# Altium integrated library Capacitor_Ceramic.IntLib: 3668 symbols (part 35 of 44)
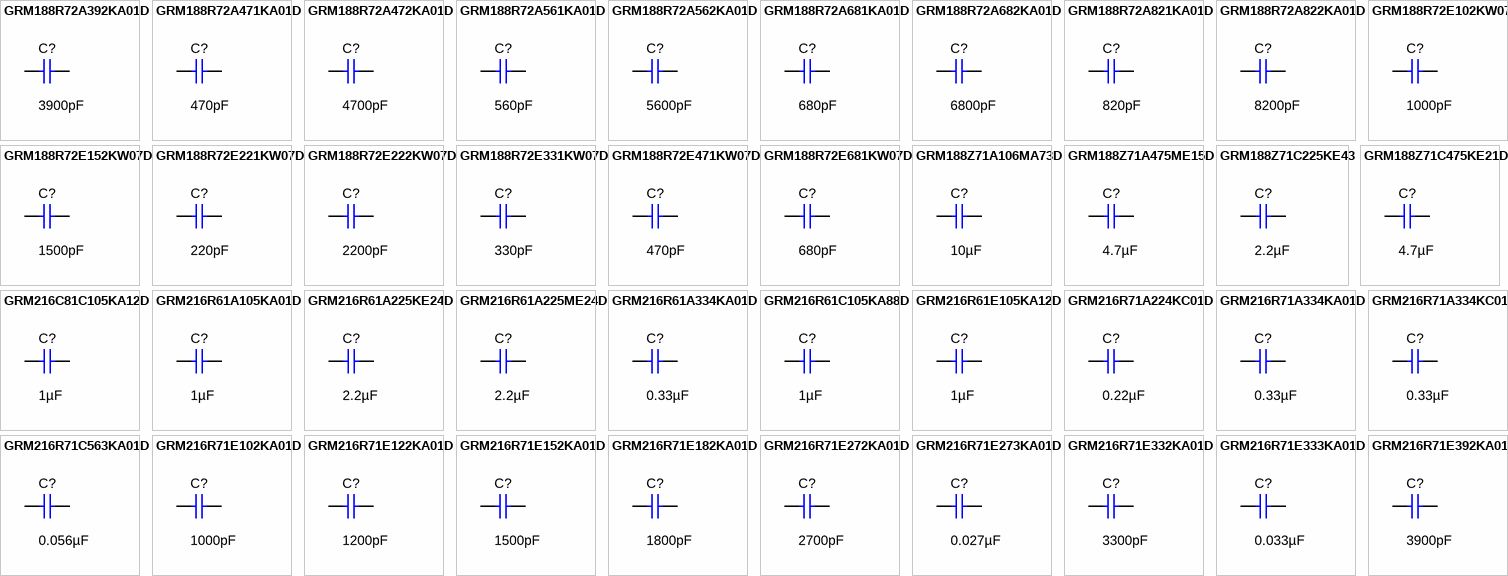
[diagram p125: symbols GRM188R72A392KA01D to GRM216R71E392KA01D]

## GRM188R72A822KA01D
designator C?  ValueDisplayed: 8200pF  (hidden comment: GRM188R72A822KA01D)
CAP, CERM, 8200 pF, 100 V,+/- 10%, X7R, 0603; Manufacturer: MuRata; Polarized: N; CompType: Capacitor; Value: 8200pF; U/M: EA; Cap_F: 0.0000000082; Tolerance_%: 10; VDC_V: 100; Value2: 100V; TaMin_C: -55; TaMax_C: 125; Cap_Case: 0603; SizeArea_mm2: 1.28; SizeAreaWB_mm2: 4.68; SizeX_mm: 1.6; SizeY_mm: 0.8; SizeZ_mm: 1; AEC Category: Q200
signal-integrity model Cap
simulation model Cap
footprint 0603
footprint 0603M
footprint 0603L
footprint 0603_HV
footprint 0603S
pins: 1, 2

## GRM188R72E102KW07D
designator C?  ValueDisplayed: 1000pF  (hidden comment: GRM188R72E102KW07D)
CAP, CERM, 1000 pF, 250 V,+/- 10%, X7R, 0603; Manufacturer: MuRata; Polarized: N; CompType: Capacitor; Value: 1000pF; U/M: EA; Cap_F: 0.000000001; Tolerance_%: 10; VDC_V: 250; Value2: 250V; TaMin_C: -55; TaMax_C: 125; Cap_Case: 0603; SizeArea_mm2: 1.28; SizeAreaWB_mm2: 4.68; SizeX_mm: 1.6; SizeY_mm: 0.8; SizeZ_mm: 1; AEC Category: Q200
signal-integrity model Cap
simulation model Cap
footprint 0603
footprint 0603M
footprint 0603L
footprint 0603_HV
footprint 0603S
pins: 1, 2

## GRM188R72E152KW07D
designator C?  ValueDisplayed: 1500pF  (hidden comment: GRM188R72E152KW07D)
CAP, CERM, 1500 pF, 250 V,+/- 10%, X7R, 0603; Manufacturer: MuRata; Polarized: N; CompType: Capacitor; Value: 1500pF; U/M: EA; Cap_F: 0.0000000015; Tolerance_%: 10; VDC_V: 250; Value2: 250V; TaMin_C: -55; TaMax_C: 125; Cap_Case: 0603; SizeArea_mm2: 1.28; SizeAreaWB_mm2: 4.68; SizeX_mm: 1.6; SizeY_mm: 0.8; SizeZ_mm: 1; AEC Category: Q200
signal-integrity model Cap
simulation model Cap
footprint 0603
footprint 0603M
footprint 0603L
footprint 0603_HV
footprint 0603S
pins: 1, 2

## GRM188R72E221KW07D
designator C?  ValueDisplayed: 220pF  (hidden comment: GRM188R72E221KW07D)
CAP, CERM, 220 pF, 250 V,+/- 10%, X7R, 0603; Manufacturer: MuRata; Polarized: N; CompType: Capacitor; Value: 220pF; U/M: EA; Cap_F: 0.00000000022; Tolerance_%: 10; VDC_V: 250; Value2: 250V; TaMin_C: -55; TaMax_C: 125; Cap_Case: 0603; SizeArea_mm2: 1.28; SizeAreaWB_mm2: 4.68; SizeX_mm: 1.6; SizeY_mm: 0.8; SizeZ_mm: 1; AEC Category: Q200
signal-integrity model Cap
simulation model Cap
footprint 0603
footprint 0603M
footprint 0603L
footprint 0603_HV
footprint 0603S
pins: 1, 2

## GRM188R72E222KW07D
designator C?  ValueDisplayed: 2200pF  (hidden comment: GRM188R72E222KW07D)
CAP, CERM, 2200 pF, 250 V,+/- 10%, X7R, 0603; Manufacturer: MuRata; Polarized: N; CompType: Capacitor; Value: 2200pF; U/M: EA; Cap_F: 0.0000000022; Tolerance_%: 10; VDC_V: 250; Value2: 250V; TaMin_C: -55; TaMax_C: 125; Cap_Case: 0603; SizeArea_mm2: 1.28; SizeAreaWB_mm2: 4.68; SizeX_mm: 1.6; SizeY_mm: 0.8; SizeZ_mm: 1; AEC Category: Q200
signal-integrity model Cap
simulation model Cap
footprint 0603
footprint 0603M
footprint 0603L
footprint 0603_HV
footprint 0603S
pins: 1, 2

## GRM188R72E331KW07D
designator C?  ValueDisplayed: 330pF  (hidden comment: GRM188R72E331KW07D)
CAP, CERM, 330 pF, 250 V,+/- 10%, X7R, 0603; Manufacturer: MuRata; Polarized: N; CompType: Capacitor; Value: 330pF; U/M: EA; Cap_F: 0.00000000033; Tolerance_%: 10; VDC_V: 250; Value2: 250V; TaMin_C: -55; TaMax_C: 125; Cap_Case: 0603; SizeArea_mm2: 1.28; SizeAreaWB_mm2: 4.68; SizeX_mm: 1.6; SizeY_mm: 0.8; SizeZ_mm: 1; AEC Category: Q200
signal-integrity model Cap
simulation model Cap
footprint 0603
footprint 0603M
footprint 0603L
footprint 0603_HV
footprint 0603S
pins: 1, 2

## GRM188R72E471KW07D
designator C?  ValueDisplayed: 470pF  (hidden comment: GRM188R72E471KW07D)
CAP, CERM, 470 pF, 250 V,+/- 10%, X7R, 0603; Manufacturer: MuRata; Polarized: N; CompType: Capacitor; Value: 470pF; U/M: EA; Cap_F: 0.00000000047; Tolerance_%: 10; VDC_V: 250; Value2: 250V; TaMin_C: -55; TaMax_C: 125; Cap_Case: 0603; SizeArea_mm2: 1.28; SizeAreaWB_mm2: 4.68; SizeX_mm: 1.6; SizeY_mm: 0.8; SizeZ_mm: 1; AEC Category: Q200; Green_Lifecycle: Not Set; Green_REACh: Incomplete
signal-integrity model Cap
simulation model Cap
footprint 0603
footprint 0603M
footprint 0603L
footprint 0603_HV
footprint 0603S
pins: 1, 2

## GRM188R72E681KW07D
designator C?  ValueDisplayed: 680pF  (hidden comment: GRM188R72E681KW07D)
CAP, CERM, 680 pF, 250 V,+/- 10%, X7R, 0603; Manufacturer: MuRata; Polarized: N; CompType: Capacitor; Value: 680pF; U/M: EA; Cap_F: 0.00000000068; Tolerance_%: 10; VDC_V: 250; Value2: 250V; TaMin_C: -55; TaMax_C: 125; Cap_Case: 0603; SizeArea_mm2: 1.28; SizeAreaWB_mm2: 4.68; SizeX_mm: 1.6; SizeY_mm: 0.8; SizeZ_mm: 1; AEC Category: Q200
signal-integrity model Cap
simulation model Cap
footprint 0603
footprint 0603M
footprint 0603L
footprint 0603_HV
footprint 0603S
pins: 1, 2

## GRM188Z71A106MA73D
designator C?  ValueDisplayed: 10µF  (hidden comment: GRM188Z71A106MA73D)
CAP, CERM, 10 µF, 10 V,+/- 20%, X7R, 0603; Manufacturer: MuRata; Polarized: N; CompType: Capacitor; Value: 10uF; U/M: EA; Cap_F: 0.00001; Tolerance_%: 20; VDC_V: 10; Value2: 10V; TaMin_C: -55; TaMax_C: 125; Cap_Case: 0603; SizeArea_mm2: 1.28; SizeAreaWB_mm2: 4.68; SizeX_mm: 1.6; SizeY_mm: 0.8; SizeZ_mm: 1; AEC Category: Q200; Green_Lifecycle: Active; Green_REACh: Passed
signal-integrity model Cap
simulation model Cap
footprint 0603
footprint 0603M
footprint 0603L
footprint 0603_HV
footprint 0603S
pins: 1, 2

## GRM188Z71A475ME15D
designator C?  ValueDisplayed: 4.7µF  (hidden comment: GRM188Z71A475ME15D)
CAP, CERM, 4.7 µF, 10 V,+/- 20%, X7R, 0603; Manufacturer: MuRata; Polarized: N; CompType: Capacitor; Value: 4.7uF; U/M: EA; Cap_F: 0.0000047; Tolerance_%: 20; VDC_V: 10; Value2: 10V; TaMin_C: -55; TaMax_C: 125; Cap_Case: 0603; SizeArea_mm2: 1.28; SizeAreaWB_mm2: 4.68; SizeX_mm: 1.6; SizeY_mm: 0.8; SizeZ_mm: 1; AEC Category: Q200
signal-integrity model Cap
simulation model Cap
footprint 0603
footprint 0603M
footprint 0603L
footprint 0603_HV
footprint 0603S
pins: 1, 2

## GRM188Z71C225KE43
designator C?  ValueDisplayed: 2.2µF  (hidden comment: GRM188Z71C225KE43)
CAP, CERM, 2.2 µF, 16 V,+/- 10%, X7R, 0603; Manufacturer: MuRata; Polarized: N; CompType: Capacitor; Value: 2.2uF; U/M: EA; Cap_F: 0.0000022; Tolerance_%: 10; VDC_V: 16; Value2: 16V; TaMin_C: -55; TaMax_C: 125; Cap_Case: 0603; SizeArea_mm2: 1.28; SizeAreaWB_mm2: 4.68; SizeX_mm: 1.6; SizeY_mm: 0.8; SizeZ_mm: 1; AEC Category: Q200; Green_Lifecycle: Active; Green_REACh: Passed
signal-integrity model Cap
simulation model Cap
footprint 0603
footprint 0603M
footprint 0603L
footprint 0603_HV
footprint 0603S
pins: 1, 2

## GRM188Z71C475KE21D
designator C?  ValueDisplayed: 4.7µF  (hidden comment: GRM188Z71C475KE21D)
CAP, CERM, 4.7 µF, 16 V,+/- 10%, X7R, 0603; Manufacturer: MuRata; Polarized: N; CompType: Capacitor; Value: 4.7uF; U/M: EA; Cap_F: 0.0000047; Tolerance_%: 10; VDC_V: 16; Value2: 16V; TaMin_C: -55; TaMax_C: 125; Cap_Case: 0603; SizeArea_mm2: 1.28; SizeAreaWB_mm2: 4.68; SizeX_mm: 1.6; SizeY_mm: 0.8; SizeZ_mm: 1; AEC Category: Q200
signal-integrity model Cap
simulation model Cap
footprint 0603
footprint 0603M
footprint 0603L
footprint 0603_HV
footprint 0603S
pins: 1, 2

## GRM216C81C105KA12D
designator C?  ValueDisplayed: 1µF  (hidden comment: GRM216C81C105KA12D)
CAP, CERM, 1 µF, 16 V,+/- 10%, X6S, 0805; Manufacturer: MuRata; Polarized: N; CompType: Capacitor; Value: 1uF; U/M: EA; Cap_F: 0.000001; Tolerance_%: 10; VDC_V: 16; Value2: 16V; TaMin_C: -55; TaMax_C: 105; Cap_Case: 0805; SizeArea_mm2: 2.5; SizeAreaWB_mm2: 6.75; SizeX_mm: 2; SizeY_mm: 1.25; SizeZ_mm: 1.45; AEC Category: Q200
signal-integrity model Cap
simulation model Cap
footprint 0805_HV
footprint 0805_HV1
footprint 0805
footprint 0805M
footprint 0805L
pins: 1, 2

## GRM216R61A105KA01D
designator C?  ValueDisplayed: 1µF  (hidden comment: GRM216R61A105KA01D)
CAP, CERM, 1 µF, 10 V,+/- 10%, X5R, 0805; Manufacturer: MuRata; Polarized: N; CompType: Capacitor; Value: 1uF; U/M: EA; Cap_F: 0.000001; Tolerance_%: 10; Value2: 10V; TaMin_C: -55; TaMax_C: 85; Cap_Case: 0805; SizeArea_mm2: 2.5; SizeAreaWB_mm2: 6.75; SizeX_mm: 2; SizeY_mm: 1.25; SizeZ_mm: 1.45; AEC Category: Q200; Green_Lifecycle: Active; Green_REACh: Passed
signal-integrity model Cap
simulation model Cap
footprint 0805_HV
footprint 0805_HV1
footprint 0805
footprint 0805M
footprint 0805L
pins: 1, 2

## GRM216R61A225KE24D
designator C?  ValueDisplayed: 2.2µF  (hidden comment: GRM216R61A225KE24D)
CAP, CERM, 2.2 µF, 10 V,+/- 10%, X5R, 0805; Manufacturer: MuRata; Polarized: N; CompType: Capacitor; Value: 2.2uF; U/M: EA; Cap_F: 0.0000022; Tolerance_%: 10; ESR_ohm: 0.009; Value1: 0.009 ohm; Value2: 10V; TaMin_C: -55; TaMax_C: 85; Cap_Case: 0805; SizeArea_mm2: 2.5; SizeAreaWB_mm2: 6.75; SizeX_mm: 2; SizeY_mm: 1.25; SizeZ_mm: 1.45; AEC Category: Q200; Green_Lifecycle: Active; Green_REACh: Passed
signal-integrity model Cap
simulation model Cap
footprint 0805_HV
footprint 0805_HV1
footprint 0805
footprint 0805M
footprint 0805L
pins: 1, 2

## GRM216R61A225ME24D
designator C?  ValueDisplayed: 2.2µF  (hidden comment: GRM216R61A225ME24D)
CAP, CERM, 2.2 µF, 10 V,+/- 20%, X5R, 0805; Manufacturer: MuRata; Polarized: N; CompType: Capacitor; Value: 2.2uF; U/M: EA; Cap_F: 0.0000022; Tolerance_%: 20; ESR_ohm: 0.009; Value1: 0.009 ohm; VDC_V: 10; Value2: 10V; TaMin_C: -55; TaMax_C: 85; Cap_Case: 0805; SizeArea_mm2: 2.5; SizeAreaWB_mm2: 6.75; SizeX_mm: 2; SizeY_mm: 1.25; SizeZ_mm: 1.45; AEC Category: Q200
signal-integrity model Cap
simulation model Cap
footprint 0805_HV
footprint 0805_HV1
footprint 0805
footprint 0805M
footprint 0805L
pins: 1, 2

## GRM216R61A334KA01D
designator C?  ValueDisplayed: 0.33µF  (hidden comment: GRM216R61A334KA01D)
CAP, CERM, 0.33 µF, 10 V,+/- 10%, X5R, 0805; Manufacturer: MuRata; Polarized: N; CompType: Capacitor; Value: 0.33uF; U/M: EA; Cap_F: 0.00000033; Tolerance_%: 10; Value2: 10V; TaMin_C: -55; TaMax_C: 85; Cap_Case: 0805; SizeArea_mm2: 2.5; SizeAreaWB_mm2: 6.75; SizeX_mm: 2; SizeY_mm: 1.25; SizeZ_mm: 1.45; AEC Category: Q200
signal-integrity model Cap
simulation model Cap
footprint 0805_HV
footprint 0805_HV1
footprint 0805
footprint 0805M
footprint 0805L
pins: 1, 2

## GRM216R61C105KA88D
designator C?  ValueDisplayed: 1µF  (hidden comment: GRM216R61C105KA88D)
CAP, CERM, 1 µF, 16 V,+/- 10%, X5R, 0805; Manufacturer: MuRata; Polarized: N; CompType: Capacitor; Value: 1uF; U/M: EA; Cap_F: 0.000001; Tolerance_%: 10; VDC_V: 16; Value2: 16V; TaMin_C: -55; TaMax_C: 85; Cap_Case: 0805; SizeArea_mm2: 2.5; SizeAreaWB_mm2: 6.75; SizeX_mm: 2; SizeY_mm: 1.25; SizeZ_mm: 1.45; AEC Category: Q200
signal-integrity model Cap
simulation model Cap
footprint 0805_HV
footprint 0805_HV1
footprint 0805
footprint 0805M
footprint 0805L
pins: 1, 2

## GRM216R61E105KA12D
designator C?  ValueDisplayed: 1µF  (hidden comment: GRM216R61E105KA12D)
CAP, CERM, 1 µF, 25 V,+/- 10%, X5R, 0805; Manufacturer: MuRata; Polarized: N; CompType: Capacitor; Value: 1uF; U/M: EA; Cap_F: 0.000001; Tolerance_%: 10; ESR_ohm: 0.009; Value1: 0.009 ohm; VDC_V: 25; Value2: 25V; TaMin_C: -55; TaMax_C: 85; Cap_Case: 0805; SizeArea_mm2: 2.5; SizeAreaWB_mm2: 6.75; SizeX_mm: 2; SizeY_mm: 1.25; SizeZ_mm: 1.45; AEC Category: Q200; Green_Lifecycle: Active; Green_REACh: Passed
signal-integrity model Cap
simulation model Cap
footprint 0805_HV
footprint 0805_HV1
footprint 0805
footprint 0805M
footprint 0805L
pins: 1, 2

## GRM216R71A224KC01D
designator C?  ValueDisplayed: 0.22µF  (hidden comment: GRM216R71A224KC01D)
CAP, CERM, 0.22 µF, 10 V,+/- 10%, X7R, 0805; Manufacturer: MuRata; Polarized: N; CompType: Capacitor; Value: 0.22uF; U/M: EA; Cap_F: 0.00000022; Tolerance_%: 10; Value2: 10V; TaMin_C: -55; TaMax_C: 125; Cap_Case: 0805; SizeArea_mm2: 2.5; SizeAreaWB_mm2: 6.75; SizeX_mm: 2; SizeY_mm: 1.25; SizeZ_mm: 1.45; AEC Category: Q200
signal-integrity model Cap
simulation model Cap
footprint 0805_HV
footprint 0805_HV1
footprint 0805
footprint 0805M
footprint 0805L
pins: 1, 2

## GRM216R71A334KA01D
designator C?  ValueDisplayed: 0.33µF  (hidden comment: GRM216R71A334KA01D)
CAP, CERM, 0.33 µF, 10 V,+/- 10%, X7R, 0805; Manufacturer: MuRata; Polarized: N; CompType: Capacitor; Value: 0.33uF; U/M: EA; Cap_F: 0.00000033; Tolerance_%: 10; Value2: 10V; TaMin_C: -55; TaMax_C: 125; Cap_Case: 0805; SizeArea_mm2: 2.5; SizeAreaWB_mm2: 6.75; SizeX_mm: 2; SizeY_mm: 1.25; SizeZ_mm: 1.45; AEC Category: Q200
signal-integrity model Cap
simulation model Cap
footprint 0805_HV
footprint 0805_HV1
footprint 0805
footprint 0805M
footprint 0805L
pins: 1, 2

## GRM216R71A334KC01D
designator C?  ValueDisplayed: 0.33µF  (hidden comment: GRM216R71A334KC01D)
CAP, CERM, 0.33 µF, 10 V,+/- 10%, X7R, 0805; Manufacturer: MuRata; Polarized: N; CompType: Capacitor; Value: 0.33uF; U/M: EA; Cap_F: 0.00000033; Tolerance_%: 10; Value2: 10V; TaMin_C: -55; TaMax_C: 125; Cap_Case: 0805; SizeArea_mm2: 2.5; SizeAreaWB_mm2: 6.75; SizeX_mm: 2; SizeY_mm: 1.25; SizeZ_mm: 1.45; AEC Category: Q200
signal-integrity model Cap
simulation model Cap
footprint 0805_HV
footprint 0805_HV1
footprint 0805
footprint 0805M
footprint 0805L
pins: 1, 2

## GRM216R71C563KA01D
designator C?  ValueDisplayed: 0.056µF  (hidden comment: GRM216R71C563KA01D)
CAP, CERM, 0.056 µF, 16 V,+/- 10%, X7R, 0805; Manufacturer: MuRata; Polarized: N; CompType: Capacitor; Value: 0.056uF; U/M: EA; Cap_F: 0.000000056; Tolerance_%: 10; VDC_V: 16; Value2: 16V; TaMin_C: -55; TaMax_C: 125; Cap_Case: 0805; SizeArea_mm2: 2.5; SizeAreaWB_mm2: 6.75; SizeX_mm: 2; SizeY_mm: 1.25; SizeZ_mm: 1.45; AEC Category: Q200
signal-integrity model Cap
simulation model Cap
footprint 0805_HV
footprint 0805_HV1
footprint 0805
footprint 0805M
footprint 0805L
pins: 1, 2

## GRM216R71E102KA01D
designator C?  ValueDisplayed: 1000pF  (hidden comment: GRM216R71E102KA01D)
CAP, CERM, 1000 pF, 25 V,+/- 10%, X7R, 0805; Manufacturer: MuRata; Polarized: N; CompType: Capacitor; Value: 1000pF; U/M: EA; Cap_F: 0.000000001; Tolerance_%: 10; VDC_V: 25; Value2: 25V; TaMin_C: -55; TaMax_C: 125; Cap_Case: 0805; SizeArea_mm2: 2.5; SizeAreaWB_mm2: 6.75; SizeX_mm: 2; SizeY_mm: 1.25; SizeZ_mm: 1.45; AEC Category: Q200; Green_Lifecycle: Active; Green_REACh: Passed
signal-integrity model Cap
simulation model Cap
footprint 0805_HV
footprint 0805_HV1
footprint 0805
footprint 0805M
footprint 0805L
pins: 1, 2

## GRM216R71E122KA01D
designator C?  ValueDisplayed: 1200pF  (hidden comment: GRM216R71E122KA01D)
CAP, CERM, 1200 pF, 25 V,+/- 10%, X7R, 0805; Manufacturer: MuRata; Polarized: N; CompType: Capacitor; Value: 1200pF; U/M: EA; Cap_F: 0.0000000012; Tolerance_%: 10; VDC_V: 25; Value2: 25V; TaMin_C: -55; TaMax_C: 125; Cap_Case: 0805; SizeArea_mm2: 2.5; SizeAreaWB_mm2: 6.75; SizeX_mm: 2; SizeY_mm: 1.25; SizeZ_mm: 1.45; AEC Category: Q200
signal-integrity model Cap
simulation model Cap
footprint 0805_HV
footprint 0805_HV1
footprint 0805
footprint 0805M
footprint 0805L
pins: 1, 2

## GRM216R71E152KA01D
designator C?  ValueDisplayed: 1500pF  (hidden comment: GRM216R71E152KA01D)
CAP, CERM, 1500 pF, 25 V,+/- 10%, X7R, 0805; Manufacturer: MuRata; Polarized: N; CompType: Capacitor; Value: 1500pF; U/M: EA; Cap_F: 0.0000000015; Tolerance_%: 10; VDC_V: 25; Value2: 25V; TaMin_C: -55; TaMax_C: 125; Cap_Case: 0805; SizeArea_mm2: 2.5; SizeAreaWB_mm2: 6.75; SizeX_mm: 2; SizeY_mm: 1.25; SizeZ_mm: 1.45; AEC Category: Q200
signal-integrity model Cap
simulation model Cap
footprint 0805_HV
footprint 0805_HV1
footprint 0805
footprint 0805M
footprint 0805L
pins: 1, 2

## GRM216R71E182KA01D
designator C?  ValueDisplayed: 1800pF  (hidden comment: GRM216R71E182KA01D)
CAP, CERM, 1800 pF, 25 V,+/- 10%, X7R, 0805; Manufacturer: MuRata; Polarized: N; CompType: Capacitor; Value: 1800pF; U/M: EA; Cap_F: 0.0000000018; Tolerance_%: 10; VDC_V: 25; Value2: 25V; TaMin_C: -55; TaMax_C: 125; Cap_Case: 0805; SizeArea_mm2: 2.5; SizeAreaWB_mm2: 6.75; SizeX_mm: 2; SizeY_mm: 1.25; SizeZ_mm: 1.45; AEC Category: Q200
signal-integrity model Cap
simulation model Cap
footprint 0805_HV
footprint 0805_HV1
footprint 0805
footprint 0805M
footprint 0805L
pins: 1, 2

## GRM216R71E272KA01D
designator C?  ValueDisplayed: 2700pF  (hidden comment: GRM216R71E272KA01D)
CAP, CERM, 2700 pF, 25 V,+/- 10%, X7R, 0805; Manufacturer: MuRata; Polarized: N; CompType: Capacitor; Value: 2700pF; U/M: EA; Cap_F: 0.0000000027; Tolerance_%: 10; VDC_V: 25; Value2: 25V; TaMin_C: -55; TaMax_C: 125; Cap_Case: 0805; SizeArea_mm2: 2.5; SizeAreaWB_mm2: 6.75; SizeX_mm: 2; SizeY_mm: 1.25; SizeZ_mm: 1.45; AEC Category: Q200
signal-integrity model Cap
simulation model Cap
footprint 0805_HV
footprint 0805_HV1
footprint 0805
footprint 0805M
footprint 0805L
pins: 1, 2

## GRM216R71E273KA01D
designator C?  ValueDisplayed: 0.027µF  (hidden comment: GRM216R71E273KA01D)
CAP, CERM, 0.027 µF, 25 V,+/- 10%, X7R, 0805; Manufacturer: MuRata; Polarized: N; CompType: Capacitor; Value: 0.027uF; U/M: EA; Cap_F: 0.000000027; Tolerance_%: 10; VDC_V: 25; Value2: 25V; TaMin_C: -55; TaMax_C: 125; Cap_Case: 0805; SizeArea_mm2: 2.5; SizeAreaWB_mm2: 6.75; SizeX_mm: 2; SizeY_mm: 1.25; SizeZ_mm: 1.45; AEC Category: Q200
signal-integrity model Cap
simulation model Cap
footprint 0805_HV
footprint 0805_HV1
footprint 0805
footprint 0805M
footprint 0805L
pins: 1, 2

## GRM216R71E332KA01D
designator C?  ValueDisplayed: 3300pF  (hidden comment: GRM216R71E332KA01D)
CAP, CERM, 3300 pF, 25 V,+/- 10%, X7R, 0805; Manufacturer: MuRata; Polarized: N; CompType: Capacitor; Value: 3300pF; U/M: EA; Cap_F: 0.0000000033; Tolerance_%: 10; VDC_V: 25; Value2: 25V; TaMin_C: -55; TaMax_C: 125; Cap_Case: 0805; SizeArea_mm2: 2.5; SizeAreaWB_mm2: 6.75; SizeX_mm: 2; SizeY_mm: 1.25; SizeZ_mm: 1.45; AEC Category: Q200
signal-integrity model Cap
simulation model Cap
footprint 0805_HV
footprint 0805_HV1
footprint 0805
footprint 0805M
footprint 0805L
pins: 1, 2

## GRM216R71E333KA01D
designator C?  ValueDisplayed: 0.033µF  (hidden comment: GRM216R71E333KA01D)
CAP, CERM, 0.033 µF, 25 V,+/- 10%, X7R, 0805; Manufacturer: MuRata; Polarized: N; CompType: Capacitor; Value: 0.033uF; U/M: EA; Cap_F: 0.000000033; Tolerance_%: 10; VDC_V: 25; Value2: 25V; TaMin_C: -55; TaMax_C: 125; Cap_Case: 0805; SizeArea_mm2: 2.5; SizeAreaWB_mm2: 6.75; SizeX_mm: 2; SizeY_mm: 1.25; SizeZ_mm: 1.45; AEC Category: Q200; Green_Lifecycle: Active; Green_REACh: Passed
signal-integrity model Cap
simulation model Cap
footprint 0805_HV
footprint 0805_HV1
footprint 0805
footprint 0805M
footprint 0805L
pins: 1, 2

## GRM216R71E392KA01D
designator C?  ValueDisplayed: 3900pF  (hidden comment: GRM216R71E392KA01D)
CAP, CERM, 3900 pF, 25 V,+/- 10%, X7R, 0805; Manufacturer: MuRata; Polarized: N; CompType: Capacitor; Value: 3900pF; U/M: EA; Cap_F: 0.0000000039; Tolerance_%: 10; VDC_V: 25; Value2: 25V; TaMin_C: -55; TaMax_C: 125; Cap_Case: 0805; SizeArea_mm2: 2.5; SizeAreaWB_mm2: 6.75; SizeX_mm: 2; SizeY_mm: 1.25; SizeZ_mm: 1.45; AEC Category: Q200
signal-integrity model Cap
simulation model Cap
footprint 0805_HV
footprint 0805_HV1
footprint 0805
footprint 0805M
footprint 0805L
pins: 1, 2

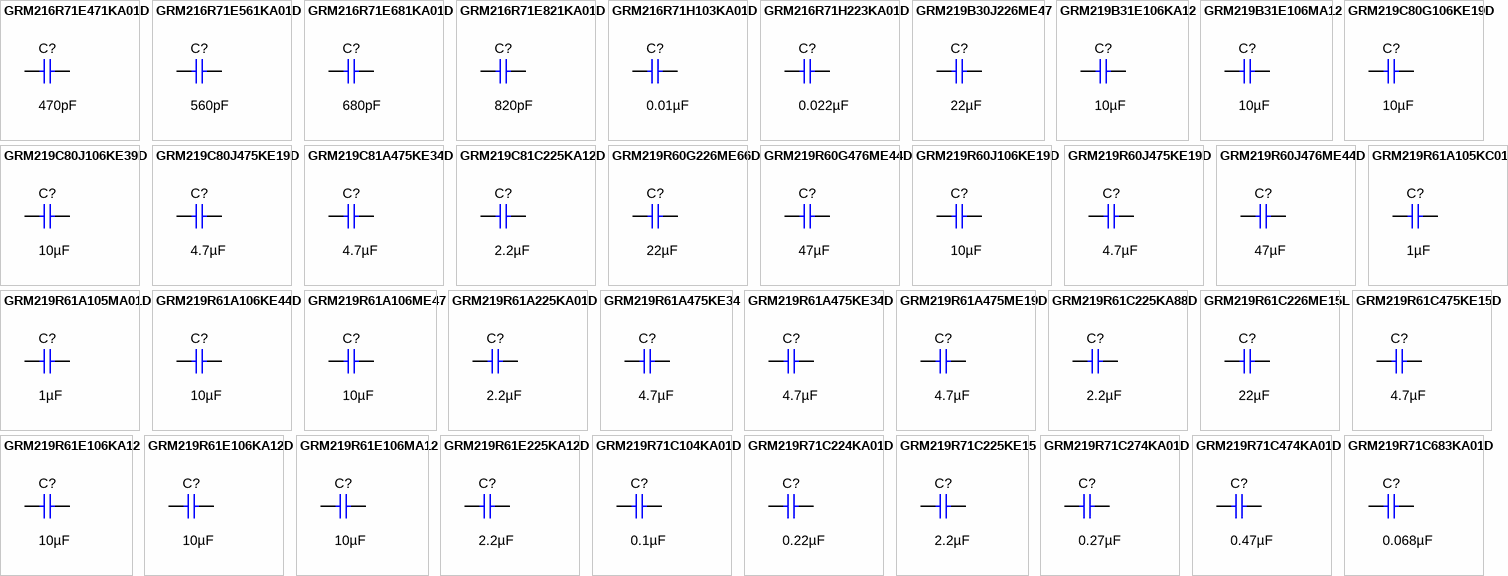
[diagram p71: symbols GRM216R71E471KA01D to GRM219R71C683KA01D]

## GRM216R71E471KA01D
designator C?  ValueDisplayed: 470pF  (hidden comment: GRM216R71E471KA01D)
CAP, CERM, 470 pF, 25 V,+/- 10%, X7R, 0805; Manufacturer: MuRata; Polarized: N; CompType: Capacitor; Value: 470pF; U/M: EA; Cap_F: 0.00000000047; Tolerance_%: 10; VDC_V: 25; Value2: 25V; TaMin_C: -55; TaMax_C: 125; Cap_Case: 0805; SizeArea_mm2: 2.5; SizeAreaWB_mm2: 6.75; SizeX_mm: 2; SizeY_mm: 1.25; SizeZ_mm: 1.45; AEC Category: Q200
signal-integrity model Cap
simulation model Cap
footprint 0805_HV
footprint 0805_HV1
footprint 0805
footprint 0805M
footprint 0805L
pins: 1, 2

## GRM216R71E561KA01D
designator C?  ValueDisplayed: 560pF  (hidden comment: GRM216R71E561KA01D)
CAP, CERM, 560 pF, 25 V,+/- 10%, X7R, 0805; Manufacturer: MuRata; Polarized: N; CompType: Capacitor; Value: 560pF; U/M: EA; Cap_F: 0.00000000056; Tolerance_%: 10; VDC_V: 25; Value2: 25V; TaMin_C: -55; TaMax_C: 125; Cap_Case: 0805; SizeArea_mm2: 2.5; SizeAreaWB_mm2: 6.75; SizeX_mm: 2; SizeY_mm: 1.25; SizeZ_mm: 1.45; AEC Category: Q200
signal-integrity model Cap
simulation model Cap
footprint 0805_HV
footprint 0805_HV1
footprint 0805
footprint 0805M
footprint 0805L
pins: 1, 2

## GRM216R71E681KA01D
designator C?  ValueDisplayed: 680pF  (hidden comment: GRM216R71E681KA01D)
CAP, CERM, 680 pF, 25 V,+/- 10%, X7R, 0805; Manufacturer: MuRata; Polarized: N; CompType: Capacitor; Value: 680pF; U/M: EA; Cap_F: 0.00000000068; Tolerance_%: 10; VDC_V: 25; Value2: 25V; TaMin_C: -55; TaMax_C: 125; Cap_Case: 0805; SizeArea_mm2: 2.5; SizeAreaWB_mm2: 6.75; SizeX_mm: 2; SizeY_mm: 1.25; SizeZ_mm: 1.45; AEC Category: Q200
signal-integrity model Cap
simulation model Cap
footprint 0805_HV
footprint 0805_HV1
footprint 0805
footprint 0805M
footprint 0805L
pins: 1, 2

## GRM216R71E821KA01D
designator C?  ValueDisplayed: 820pF  (hidden comment: GRM216R71E821KA01D)
CAP, CERM, 820 pF, 25 V,+/- 10%, X7R, 0805; Manufacturer: MuRata; Polarized: N; CompType: Capacitor; Value: 820pF; U/M: EA; Cap_F: 0.00000000082; Tolerance_%: 10; VDC_V: 25; Value2: 25V; TaMin_C: -55; TaMax_C: 125; Cap_Case: 0805; SizeArea_mm2: 2.5; SizeAreaWB_mm2: 6.75; SizeX_mm: 2; SizeY_mm: 1.25; SizeZ_mm: 1.45; AEC Category: Q200
signal-integrity model Cap
simulation model Cap
footprint 0805_HV
footprint 0805_HV1
footprint 0805
footprint 0805M
footprint 0805L
pins: 1, 2

## GRM216R71H103KA01D
designator C?  ValueDisplayed: 0.01µF  (hidden comment: GRM216R71H103KA01D)
CAP, CERM, 0.01 µF, 50 V,+/- 10%, X7R, 0805; Manufacturer: MuRata; Polarized: N; CompType: Capacitor; Value: 0.01uF; U/M: EA; Cap_F: 0.00000001; Tolerance_%: 10; VDC_V: 50; Value2: 50V; TaMin_C: -55; TaMax_C: 125; Cap_Case: 0805; SizeArea_mm2: 2.5; SizeAreaWB_mm2: 6.75; SizeX_mm: 2; SizeY_mm: 1.25; SizeZ_mm: 1.45; AEC Category: Q200; Green_Lifecycle: Active; Green_REACh: Passed
signal-integrity model Cap
simulation model Cap
footprint 0805_HV
footprint 0805_HV1
footprint 0805
footprint 0805M
footprint 0805L
pins: 1, 2

## GRM216R71H223KA01D
designator C?  ValueDisplayed: 0.022µF  (hidden comment: GRM216R71H223KA01D)
CAP, CERM, 0.022 µF, 50 V,+/- 10%, X7R, 0805; Manufacturer: MuRata; Polarized: N; CompType: Capacitor; Value: 0.022uF; U/M: EA; Cap_F: 0.000000022; Tolerance_%: 10; VDC_V: 50; Value2: 50V; TaMin_C: -55; TaMax_C: 125; Cap_Case: 0805; SizeArea_mm2: 2.5; SizeAreaWB_mm2: 6.75; SizeX_mm: 2; SizeY_mm: 1.25; SizeZ_mm: 1.45; AEC Category: Q200; Green_Lifecycle: Active; Green_REACh: Passed
signal-integrity model Cap
simulation model Cap
footprint 0805_HV
footprint 0805_HV1
footprint 0805
footprint 0805M
footprint 0805L
pins: 1, 2

## GRM219B30J226ME47
designator C?  ValueDisplayed: 22µF  (hidden comment: GRM219B30J226ME47)
CAP, CERM, 22 µF, 6.3 V,+/- 20%, B, 0805; Manufacturer: MuRata; Polarized: N; CompType: Capacitor; Value: 22uF; U/M: EA; Cap_F: 0.000022; Tolerance_%: 20; VDC_V: 6.3; Value2: 6.3V; TaMin_C: -25; TaMax_C: 85; Cap_Case: 0805; SizeArea_mm2: 2.5; SizeAreaWB_mm2: 6.75; SizeX_mm: 2; SizeY_mm: 1.25; SizeZ_mm: 1.45; AEC Category: Q200
signal-integrity model Cap
simulation model Cap
footprint 0805_HV
footprint 0805_HV1
footprint 0805
footprint 0805M
footprint 0805L
pins: 1, 2

## GRM219B31E106KA12
designator C?  ValueDisplayed: 10µF  (hidden comment: GRM219B31E106KA12)
CAP, CERM, 10 µF, 25 V,+/- 10%, B, 0805; Manufacturer: MuRata; Polarized: N; CompType: Capacitor; Value: 10uF; U/M: EA; Cap_F: 0.00001; Tolerance_%: 10; VDC_V: 25; Value2: 25V; TaMin_C: -25; TaMax_C: 85; Cap_Case: 0805; SizeArea_mm2: 2.5; SizeAreaWB_mm2: 6.75; SizeX_mm: 2; SizeY_mm: 1.25; SizeZ_mm: 1.45; AEC Category: Q200
signal-integrity model Cap
simulation model Cap
footprint 0805_HV
footprint 0805_HV1
footprint 0805
footprint 0805M
footprint 0805L
pins: 1, 2

## GRM219B31E106MA12
designator C?  ValueDisplayed: 10µF  (hidden comment: GRM219B31E106MA12)
CAP, CERM, 10 µF, 25 V,+/- 20%, B, 0805; Manufacturer: MuRata; Polarized: N; CompType: Capacitor; Value: 10uF; U/M: EA; Cap_F: 0.00001; Tolerance_%: 20; VDC_V: 25; Value2: 25V; TaMin_C: -25; TaMax_C: 85; Cap_Case: 0805; SizeArea_mm2: 2.5; SizeAreaWB_mm2: 6.75; SizeX_mm: 2; SizeY_mm: 1.25; SizeZ_mm: 1.45; AEC Category: Q200
signal-integrity model Cap
simulation model Cap
footprint 0805_HV
footprint 0805_HV1
footprint 0805
footprint 0805M
footprint 0805L
pins: 1, 2

## GRM219C80G106KE19D
designator C?  ValueDisplayed: 10µF  (hidden comment: GRM219C80G106KE19D)
CAP, CERM, 10 µF, 4 V,+/- 10%, X6S, 0805; Manufacturer: MuRata; Polarized: N; CompType: Capacitor; Value: 10uF; U/M: EA; Cap_F: 0.00001; Tolerance_%: 10; VDC_V: 4; Value2: 4V; TaMin_C: -55; TaMax_C: 105; Cap_Case: 0805; SizeArea_mm2: 2.5; SizeAreaWB_mm2: 6.75; SizeX_mm: 2; SizeY_mm: 1.25; SizeZ_mm: 1.45; AEC Category: Q200
signal-integrity model Cap
simulation model Cap
footprint 0805_HV
footprint 0805_HV1
footprint 0805
footprint 0805M
footprint 0805L
pins: 1, 2

## GRM219C80J106KE39D
designator C?  ValueDisplayed: 10µF  (hidden comment: GRM219C80J106KE39D)
CAP, CERM, 10 µF, 6.3 V,+/- 10%, X6S, 0805; Manufacturer: MuRata; Polarized: N; CompType: Capacitor; Value: 10uF; U/M: EA; Cap_F: 0.00001; Tolerance_%: 10; VDC_V: 6.3; Value2: 6.3V; TaMin_C: -55; TaMax_C: 105; Cap_Case: 0805; SizeArea_mm2: 2.5; SizeAreaWB_mm2: 6.75; SizeX_mm: 2; SizeY_mm: 1.25; SizeZ_mm: 1.45; AEC Category: Q200
signal-integrity model Cap
simulation model Cap
footprint 0805_HV
footprint 0805_HV1
footprint 0805
footprint 0805M
footprint 0805L
pins: 1, 2

## GRM219C80J475KE19D
designator C?  ValueDisplayed: 4.7µF  (hidden comment: GRM219C80J475KE19D)
CAP, CERM, 4.7 µF, 6.3 V,+/- 10%, X6S, 0805; Manufacturer: MuRata; Polarized: N; CompType: Capacitor; Value: 4.7uF; U/M: EA; Cap_F: 0.0000047; Tolerance_%: 10; VDC_V: 6.3; Value2: 6.3V; TaMin_C: -55; TaMax_C: 105; Cap_Case: 0805; SizeArea_mm2: 2.5; SizeAreaWB_mm2: 6.75; SizeX_mm: 2; SizeY_mm: 1.25; SizeZ_mm: 1.45; AEC Category: Q200
signal-integrity model Cap
simulation model Cap
footprint 0805_HV
footprint 0805_HV1
footprint 0805
footprint 0805M
footprint 0805L
pins: 1, 2

## GRM219C81A475KE34D
designator C?  ValueDisplayed: 4.7µF  (hidden comment: GRM219C81A475KE34D)
CAP, CERM, 4.7 µF, 10 V,+/- 10%, X6S, 0805; Manufacturer: MuRata; Polarized: N; CompType: Capacitor; Value: 4.7uF; U/M: EA; Cap_F: 0.0000047; Tolerance_%: 10; Value2: 10V; TaMin_C: -55; TaMax_C: 105; Cap_Case: 0805; SizeArea_mm2: 2.5; SizeAreaWB_mm2: 6.75; SizeX_mm: 2; SizeY_mm: 1.25; SizeZ_mm: 1.45; AEC Category: Q200
signal-integrity model Cap
simulation model Cap
footprint 0805_HV
footprint 0805_HV1
footprint 0805
footprint 0805M
footprint 0805L
pins: 1, 2

## GRM219C81C225KA12D
designator C?  ValueDisplayed: 2.2µF  (hidden comment: GRM219C81C225KA12D)
CAP, CERM, 2.2 µF, 16 V,+/- 10%, X6S, 0805; Manufacturer: MuRata; Polarized: N; CompType: Capacitor; Value: 2.2uF; U/M: EA; Cap_F: 0.0000022; Tolerance_%: 10; VDC_V: 16; Value2: 16V; TaMin_C: -55; TaMax_C: 105; Cap_Case: 0805; SizeArea_mm2: 2.5; SizeAreaWB_mm2: 6.75; SizeX_mm: 2; SizeY_mm: 1.25; SizeZ_mm: 1.45; AEC Category: Q200
signal-integrity model Cap
simulation model Cap
footprint 0805_HV
footprint 0805_HV1
footprint 0805
footprint 0805M
footprint 0805L
pins: 1, 2

## GRM219R60G226ME66D
designator C?  ValueDisplayed: 22µF  (hidden comment: GRM219R60G226ME66D)
CAP, CERM, 22 µF, 4 V,+/- 20%, X5R, 0805; Manufacturer: MuRata; Polarized: N; CompType: Capacitor; Value: 22uF; U/M: EA; Cap_F: 0.000022; Tolerance_%: 20; VDC_V: 4; Value2: 4V; TaMin_C: -55; TaMax_C: 85; Cap_Case: 0805; SizeArea_mm2: 2.5; SizeAreaWB_mm2: 6.75; SizeX_mm: 2; SizeY_mm: 1.25; SizeZ_mm: 1.45; AEC Category: Q200
signal-integrity model Cap
simulation model Cap
footprint 0805_HV
footprint 0805_HV1
footprint 0805
footprint 0805M
footprint 0805L
pins: 1, 2

## GRM219R60G476ME44D
designator C?  ValueDisplayed: 47µF  (hidden comment: GRM219R60G476ME44D)
CAP, CERM, 47 µF, 4 V,+/- 20%, X5R, 0805; Manufacturer: MuRata; Polarized: N; CompType: Capacitor; Value: 47uF; U/M: EA; Cap_F: 0.000047; Tolerance_%: 20; VDC_V: 4; Value2: 4V; TaMin_C: -55; TaMax_C: 85; Cap_Case: 0805; SizeArea_mm2: 2.5; SizeAreaWB_mm2: 6.75; SizeX_mm: 2; SizeY_mm: 1.25; SizeZ_mm: 1.45; AEC Category: Q200; Green_Lifecycle: Active; Green_REACh: Passed
signal-integrity model Cap
simulation model Cap
footprint 0805_HV
footprint 0805_HV1
footprint 0805
footprint 0805M
footprint 0805L
pins: 1, 2

## GRM219R60J106KE19D
designator C?  ValueDisplayed: 10µF  (hidden comment: GRM219R60J106KE19D)
CAP, CERM, 10 µF, 6.3 V,+/- 10%, X5R, 0805; Manufacturer: MuRata; Polarized: N; CompType: Capacitor; Value: 10uF; U/M: EA; Cap_F: 0.00001; Tolerance_%: 10; ESR_ohm: 0.003; Value1: 0.003 ohm; VDC_V: 6.3; Value2: 6.3V; TaMin_C: -55; TaMax_C: 85; Cap_Case: 0805; SizeArea_mm2: 2.5; SizeAreaWB_mm2: 6.75; SizeX_mm: 2; SizeY_mm: 1.25; SizeZ_mm: 1.45; AEC Category: Q200; Green_Lifecycle: Active; Green_REACh: Passed
signal-integrity model Cap
simulation model Cap
footprint 0805_HV
footprint 0805_HV1
footprint 0805
footprint 0805M
footprint 0805L
pins: 1, 2

## GRM219R60J475KE19D
designator C?  ValueDisplayed: 4.7µF  (hidden comment: GRM219R60J475KE19D)
CAP, CERM, 4.7 µF, 6.3 V,+/- 10%, X5R, 0805; Manufacturer: MuRata; Polarized: N; CompType: Capacitor; Value: 4.7uF; U/M: EA; Cap_F: 0.0000047; Tolerance_%: 10; VDC_V: 6.3; Value2: 6.3V; TaMin_C: -55; TaMax_C: 85; Cap_Case: 0805; SizeArea_mm2: 2.5; SizeAreaWB_mm2: 6.75; SizeX_mm: 2; SizeY_mm: 1.25; SizeZ_mm: 1.45; AEC Category: Q200; Green_Lifecycle: Active; Green_REACh: Passed
signal-integrity model Cap
simulation model Cap
footprint 0805_HV
footprint 0805_HV1
footprint 0805
footprint 0805M
footprint 0805L
pins: 1, 2

## GRM219R60J476ME44D
designator C?  ValueDisplayed: 47µF  (hidden comment: GRM219R60J476ME44D)
CAP, CERM, 47 µF, 6.3 V,+/- 20%, X5R, 0805; Manufacturer: MuRata; Polarized: N; CompType: Capacitor; Value: 47uF; U/M: EA; Cap_F: 0.000047; Tolerance_%: 20; VDC_V: 6.3; Value2: 6.3V; TaMin_C: -55; TaMax_C: 85; Cap_Case: 0805; SizeArea_mm2: 2.5; SizeAreaWB_mm2: 6.75; SizeX_mm: 2; SizeY_mm: 1.25; SizeZ_mm: 1.45; AEC Category: Q200; Green_Lifecycle: Active; Green_REACh: Passed
signal-integrity model Cap
simulation model Cap
footprint 0805_HV
footprint 0805_HV1
footprint 0805
footprint 0805M
footprint 0805L
pins: 1, 2

## GRM219R61A105KC01D
designator C?  ValueDisplayed: 1µF  (hidden comment: GRM219R61A105KC01D)
CAP, CERM, 1 µF, 10 V,+/- 10%, X5R, 0805; Manufacturer: MuRata; Polarized: N; CompType: Capacitor; Value: 1uF; U/M: EA; Cap_F: 0.000001; Tolerance_%: 10; ESR_ohm: 0.004; Value1: 0.004 ohm; Value2: 10V; TaMin_C: -55; TaMax_C: 85; Cap_Case: 0805; SizeArea_mm2: 2.5; SizeAreaWB_mm2: 6.75; SizeX_mm: 2; SizeY_mm: 1.25; SizeZ_mm: 1.45; AEC Category: Q200
signal-integrity model Cap
simulation model Cap
footprint 0805_HV
footprint 0805_HV1
footprint 0805
footprint 0805M
footprint 0805L
pins: 1, 2

## GRM219R61A105MA01D
designator C?  ValueDisplayed: 1µF  (hidden comment: GRM219R61A105MA01D)
CAP, CERM, 1 µF, 10 V,+/- 20%, X5R, 0805; Manufacturer: MuRata; Polarized: N; CompType: Capacitor; Value: 1uF; U/M: EA; Cap_F: 0.000001; Tolerance_%: 20; ESR_ohm: 0.004; Value1: 0.004 ohm; VDC_V: 10; Value2: 10V; TaMin_C: -55; TaMax_C: 85; Cap_Case: 0805; SizeArea_mm2: 2.5; SizeAreaWB_mm2: 6.75; SizeX_mm: 2; SizeY_mm: 1.25; SizeZ_mm: 1.45; AEC Category: Q200
signal-integrity model Cap
simulation model Cap
footprint 0805_HV
footprint 0805_HV1
footprint 0805
footprint 0805M
footprint 0805L
pins: 1, 2

## GRM219R61A106KE44D
designator C?  ValueDisplayed: 10µF  (hidden comment: GRM219R61A106KE44D)
CAP, CERM, 10 µF, 10 V,+/- 10%, X5R, 0805; Manufacturer: MuRata; Polarized: N; CompType: Capacitor; Value: 10uF; U/M: EA; Cap_F: 0.00001; Tolerance_%: 10; ESR_ohm: 0.005; Value1: 0.005 ohm; Value2: 10V; TaMin_C: -55; TaMax_C: 85; Cap_Case: 0805; SizeArea_mm2: 2.5; SizeAreaWB_mm2: 6.75; SizeX_mm: 2; SizeY_mm: 1.25; SizeZ_mm: 1.45; AEC Category: Q200; Green_Lifecycle: Active; Green_REACh: Passed
signal-integrity model Cap
simulation model Cap
footprint 0805_HV
footprint 0805_HV1
footprint 0805
footprint 0805M
footprint 0805L
pins: 1, 2

## GRM219R61A106ME47
designator C?  ValueDisplayed: 10µF  (hidden comment: GRM219R61A106ME47)
CAP, CERM, 10 µF, 10 V,+/- 20%, X5R, 0805; Manufacturer: MuRata; Polarized: N; CompType: Capacitor; Value: 10uF; U/M: EA; Cap_F: 0.00001; Tolerance_%: 20; VDC_V: 10; Value2: 10V; TaMin_C: -55; TaMax_C: 85; Cap_Case: 0805; SizeArea_mm2: 2.5; SizeAreaWB_mm2: 6.75; SizeX_mm: 2; SizeY_mm: 1.25; SizeZ_mm: 1.45; AEC Category: Q200; Green_Lifecycle: Active; Green_REACh: Passed
signal-integrity model Cap
simulation model Cap
footprint 0805_HV
footprint 0805_HV1
footprint 0805
footprint 0805M
footprint 0805L
pins: 1, 2

## GRM219R61A225KA01D
designator C?  ValueDisplayed: 2.2µF  (hidden comment: GRM219R61A225KA01D)
CAP, CERM, 2.2 µF, 10 V,+/- 10%, X5R, 0805; Manufacturer: MuRata; Polarized: N; CompType: Capacitor; Value: 2.2uF; U/M: EA; Cap_F: 0.0000022; Tolerance_%: 10; Value2: 10V; TaMin_C: -55; TaMax_C: 85; Cap_Case: 0805; SizeArea_mm2: 2.5; SizeAreaWB_mm2: 6.75; SizeX_mm: 2; SizeY_mm: 1.25; SizeZ_mm: 1.45; AEC Category: Q200
signal-integrity model Cap
simulation model Cap
footprint 0805_HV
footprint 0805_HV1
footprint 0805
footprint 0805M
footprint 0805L
pins: 1, 2

## GRM219R61A475KE34
designator C?  ValueDisplayed: 4.7µF  (hidden comment: GRM219R61A475KE34)
CAP, CERM, 4.7 µF, 10 V,+/- 10%, X5R, 0805; Manufacturer: MuRata; Polarized: N; CompType: Capacitor; Value: 4.7uF; U/M: EA; Cap_F: 0.0000047; Tolerance_%: 10; Value2: 10V; TaMin_C: -55; TaMax_C: 85; Cap_Case: 0805; SizeArea_mm2: 2.5; SizeAreaWB_mm2: 6.75; SizeX_mm: 2; SizeY_mm: 1.25; SizeZ_mm: 1.45; AEC Category: Q200; Green_Lifecycle: Active; Green_REACh: Passed
signal-integrity model Cap
simulation model Cap
footprint 0805_HV
footprint 0805_HV1
footprint 0805
footprint 0805M
footprint 0805L
pins: 1, 2

## GRM219R61A475KE34D
designator C?  ValueDisplayed: 4.7µF  (hidden comment: GRM219R61A475KE34D)
CAP, CERM, 4.7 µF, 10 V,+/- 10%, X5R, 0805; Manufacturer: MuRata; Polarized: N; CompType: Capacitor; Value: 4.7uF; U/M: EA; Cap_F: 0.0000047; Tolerance_%: 10; ESR_ohm: 0.004; Value1: 0.004 ohm; Value2: 10V; TaMin_C: -55; TaMax_C: 85; Cap_Case: 0805; SizeArea_mm2: 2.5; SizeAreaWB_mm2: 6.75; SizeX_mm: 2; SizeY_mm: 1.25; SizeZ_mm: 1.45; AEC Category: Q200; Green_Lifecycle: Active; Green_REACh: Passed
signal-integrity model Cap
simulation model Cap
footprint 0805_HV
footprint 0805_HV1
footprint 0805
footprint 0805M
footprint 0805L
pins: 1, 2

## GRM219R61A475ME19D
designator C?  ValueDisplayed: 4.7µF  (hidden comment: GRM219R61A475ME19D)
CAP, CERM, 4.7 µF, 10 V,+/- 20%, X5R, 0805; Manufacturer: MuRata; Polarized: N; CompType: Capacitor; Value: 4.7uF; U/M: EA; Cap_F: 0.0000047; Tolerance_%: 20; ESR_ohm: 0.004; Value1: 0.004 ohm; VDC_V: 10; Value2: 10V; TaMin_C: -55; TaMax_C: 85; Cap_Case: 0805; SizeArea_mm2: 2.5; SizeAreaWB_mm2: 6.75; SizeX_mm: 2; SizeY_mm: 1.25; SizeZ_mm: 1.45; AEC Category: Q200
signal-integrity model Cap
simulation model Cap
footprint 0805_HV
footprint 0805_HV1
footprint 0805
footprint 0805M
footprint 0805L
pins: 1, 2

## GRM219R61C225KA88D
designator C?  ValueDisplayed: 2.2µF  (hidden comment: GRM219R61C225KA88D)
CAP, CERM, 2.2 µF, 16 V,+/- 10%, X5R, 0805; Manufacturer: MuRata; Polarized: N; CompType: Capacitor; Value: 2.2uF; U/M: EA; Cap_F: 0.0000022; Tolerance_%: 10; ESR_ohm: 0.006; Value1: 0.006 ohm; VDC_V: 16; Value2: 16V; TaMin_C: -55; TaMax_C: 85; Cap_Case: 0805; SizeArea_mm2: 2.5; SizeAreaWB_mm2: 6.75; SizeX_mm: 2; SizeY_mm: 1.25; SizeZ_mm: 1.45; AEC Category: Q200
signal-integrity model Cap
simulation model Cap
footprint 0805_HV
footprint 0805_HV1
footprint 0805
footprint 0805M
footprint 0805L
pins: 1, 2

## GRM219R61C226ME15L
designator C?  ValueDisplayed: 22µF  (hidden comment: GRM219R61C226ME15L)
CAP, CERM, 22 µF, 16 V,+/- 20%, X5R, 0805; Manufacturer: MuRata; Polarized: N; CompType: Capacitor; Value: 22uF; U/M: EA; Cap_F: 0.000022; Tolerance_%: 20; VDC_V: 16; Value2: 16V; TaMin_C: -55; TaMax_C: 85; Cap_Case: 0805; SizeArea_mm2: 2.5; SizeAreaWB_mm2: 6.75; SizeX_mm: 2; SizeY_mm: 1.25; SizeZ_mm: 1.45; AEC Category: Q200
signal-integrity model Cap
simulation model Cap
footprint 0805_HV
footprint 0805_HV1
footprint 0805
footprint 0805M
footprint 0805L
pins: 1, 2

## GRM219R61C475KE15D
designator C?  ValueDisplayed: 4.7µF  (hidden comment: GRM219R61C475KE15D)
CAP, CERM, 4.7 µF, 16 V,+/- 10%, X5R, 0805; Manufacturer: MuRata; Polarized: N; CompType: Capacitor; Value: 4.7uF; U/M: EA; Cap_F: 0.0000047; Tolerance_%: 10; VDC_V: 16; Value2: 16V; TaMin_C: -55; TaMax_C: 85; Cap_Case: 0805; SizeArea_mm2: 2.5; SizeAreaWB_mm2: 6.75; SizeX_mm: 2; SizeY_mm: 1.25; SizeZ_mm: 1.45; AEC Category: Q200; Green_Lifecycle: Active; Green_REACh: Passed
signal-integrity model Cap
simulation model Cap
footprint 0805_HV
footprint 0805_HV1
footprint 0805
footprint 0805M
footprint 0805L
pins: 1, 2

## GRM219R61E106KA12
designator C?  ValueDisplayed: 10µF  (hidden comment: GRM219R61E106KA12)
CAP, CERM, 10 µF, 25 V,+/- 10%, X5R, 0805; Manufacturer: MuRata; Polarized: N; CompType: Capacitor; Value: 10uF; U/M: EA; Cap_F: 0.00001; Tolerance_%: 10; VDC_V: 25; Value2: 25V; TaMin_C: -55; TaMax_C: 85; Cap_Case: 0805; SizeArea_mm2: 2.5; SizeAreaWB_mm2: 6.75; SizeX_mm: 2; SizeY_mm: 1.25; SizeZ_mm: 1.45; AEC Category: Q200
signal-integrity model Cap
simulation model Cap
footprint 0805_HV
footprint 0805_HV1
footprint 0805
footprint 0805M
footprint 0805L
pins: 1, 2

## GRM219R61E106KA12D
designator C?  ValueDisplayed: 10µF  (hidden comment: GRM219R61E106KA12D)
CAP, CERM, 10 µF, 25 V,+/- 10%, X5R, 0805; Manufacturer: MuRata; Polarized: N; CompType: Capacitor; Value: 10uF; U/M: EA; Cap_F: 0.00001; Tolerance_%: 10; VDC_V: 25; Value2: 25V; TaMin_C: -55; TaMax_C: 85; Cap_Case: 0805; SizeArea_mm2: 2.5; SizeAreaWB_mm2: 6.75; SizeX_mm: 2; SizeY_mm: 1.25; SizeZ_mm: 1.45; AEC Category: Q200; Green_Lifecycle: Active; Green_REACh: Passed
signal-integrity model Cap
simulation model Cap
footprint 0805_HV
footprint 0805_HV1
footprint 0805
footprint 0805M
footprint 0805L
pins: 1, 2

## GRM219R61E106MA12
designator C?  ValueDisplayed: 10µF  (hidden comment: GRM219R61E106MA12)
CAP, CERM, 10 µF, 25 V,+/- 20%, X5R, 0805; Manufacturer: MuRata; Polarized: N; CompType: Capacitor; Value: 10uF; U/M: EA; Cap_F: 0.00001; Tolerance_%: 20; VDC_V: 25; Value2: 25V; TaMin_C: -55; TaMax_C: 85; Cap_Case: 0805; SizeArea_mm2: 2.5; SizeAreaWB_mm2: 6.75; SizeX_mm: 2; SizeY_mm: 1.25; SizeZ_mm: 1.45; AEC Category: Q200
signal-integrity model Cap
simulation model Cap
footprint 0805_HV
footprint 0805_HV1
footprint 0805
footprint 0805M
footprint 0805L
pins: 1, 2

## GRM219R61E225KA12D
designator C?  ValueDisplayed: 2.2µF  (hidden comment: GRM219R61E225KA12D)
CAP, CERM, 2.2 µF, 25 V,+/- 10%, X5R, 0805; Manufacturer: MuRata; Polarized: N; CompType: Capacitor; Value: 2.2uF; U/M: EA; Cap_F: 0.0000022; Tolerance_%: 10; ESR_ohm: 0.006; Value1: 0.006 ohm; VDC_V: 25; Value2: 25V; TaMin_C: -55; TaMax_C: 85; Cap_Case: 0805; SizeArea_mm2: 2.5; SizeAreaWB_mm2: 6.75; SizeX_mm: 2; SizeY_mm: 1.25; SizeZ_mm: 1.45; AEC Category: Q200; Green_Lifecycle: Active; Green_REACh: Passed
signal-integrity model Cap
simulation model Cap
footprint 0805_HV
footprint 0805_HV1
footprint 0805
footprint 0805M
footprint 0805L
pins: 1, 2

## GRM219R71C104KA01D
designator C?  ValueDisplayed: 0.1µF  (hidden comment: GRM219R71C104KA01D)
CAP, CERM, 0.1 µF, 16 V,+/- 10%, X7R, 0805; Manufacturer: MuRata; Polarized: N; CompType: Capacitor; Value: 0.1uF; U/M: EA; Cap_F: 0.0000001; Tolerance_%: 10; VDC_V: 16; Value2: 16V; TaMin_C: -55; TaMax_C: 125; Cap_Case: 0805; SizeArea_mm2: 2.5; SizeAreaWB_mm2: 6.75; SizeX_mm: 2; SizeY_mm: 1.25; SizeZ_mm: 1.45; AEC Category: Q200; Green_Lifecycle: Active; Green_REACh: Passed
signal-integrity model Cap
simulation model Cap
footprint 0805_HV
footprint 0805_HV1
footprint 0805
footprint 0805M
footprint 0805L
pins: 1, 2

## GRM219R71C224KA01D
designator C?  ValueDisplayed: 0.22µF  (hidden comment: GRM219R71C224KA01D)
CAP, CERM, 0.22 µF, 16 V,+/- 10%, X7R, 0805; Manufacturer: MuRata; Polarized: N; CompType: Capacitor; Value: 0.22uF; U/M: EA; Cap_F: 0.00000022; Tolerance_%: 10; VDC_V: 16; Value2: 16V; TaMin_C: -55; TaMax_C: 125; Cap_Case: 0805; SizeArea_mm2: 2.5; SizeAreaWB_mm2: 6.75; SizeX_mm: 2; SizeY_mm: 1.25; SizeZ_mm: 1.45; AEC Category: Q200; Green_Lifecycle: Active; Green_REACh: Passed
signal-integrity model Cap
simulation model Cap
footprint 0805_HV
footprint 0805_HV1
footprint 0805
footprint 0805M
footprint 0805L
pins: 1, 2

## GRM219R71C225KE15
designator C?  ValueDisplayed: 2.2µF  (hidden comment: GRM219R71C225KE15)
CAP, CERM, 2.2 µF, 16 V,+/- 10%, X7R, 0805; Manufacturer: MuRata; Polarized: N; CompType: Capacitor; Value: 2.2uF; U/M: EA; Cap_F: 0.0000022; Tolerance_%: 10; VDC_V: 16; Value2: 16V; TaMin_C: -55; TaMax_C: 125; Cap_Case: 0805; SizeArea_mm2: 2.5; SizeAreaWB_mm2: 6.75; SizeX_mm: 2; SizeY_mm: 1.25; SizeZ_mm: 1.45; AEC Category: Q200
signal-integrity model Cap
simulation model Cap
footprint 0805_HV
footprint 0805_HV1
footprint 0805
footprint 0805M
footprint 0805L
pins: 1, 2

## GRM219R71C274KA01D
designator C?  ValueDisplayed: 0.27µF  (hidden comment: GRM219R71C274KA01D)
CAP, CERM, 0.27 µF, 16 V,+/- 10%, X7R, 0805; Manufacturer: MuRata; Polarized: N; CompType: Capacitor; Value: 0.27uF; U/M: EA; Cap_F: 0.00000027; Tolerance_%: 10; VDC_V: 16; Value2: 16V; TaMin_C: -55; TaMax_C: 125; Cap_Case: 0805; SizeArea_mm2: 2.5; SizeAreaWB_mm2: 6.75; SizeX_mm: 2; SizeY_mm: 1.25; SizeZ_mm: 1.45; AEC Category: Q200
signal-integrity model Cap
simulation model Cap
footprint 0805_HV
footprint 0805_HV1
footprint 0805
footprint 0805M
footprint 0805L
pins: 1, 2

## GRM219R71C474KA01D
designator C?  ValueDisplayed: 0.47µF  (hidden comment: GRM219R71C474KA01D)
CAP, CERM, 0.47 µF, 16 V,+/- 10%, X7R, 0805; Manufacturer: MuRata; Polarized: N; CompType: Capacitor; Value: 0.47uF; U/M: EA; Cap_F: 0.00000047; Tolerance_%: 10; VDC_V: 16; Value2: 16V; TaMin_C: -55; TaMax_C: 125; Cap_Case: 0805; SizeArea_mm2: 2.5; SizeAreaWB_mm2: 6.75; SizeX_mm: 2; SizeY_mm: 1.25; SizeZ_mm: 1.45; AEC Category: Q200
signal-integrity model Cap
simulation model Cap
footprint 0805_HV
footprint 0805_HV1
footprint 0805
footprint 0805M
footprint 0805L
pins: 1, 2

## GRM219R71C683KA01D
designator C?  ValueDisplayed: 0.068µF  (hidden comment: GRM219R71C683KA01D)
CAP, CERM, 0.068 µF, 16 V,+/- 10%, X7R, 0805; Manufacturer: MuRata; Polarized: N; CompType: Capacitor; Value: 0.068uF; U/M: EA; Cap_F: 0.000000068; Tolerance_%: 10; VDC_V: 16; Value2: 16V; TaMin_C: -55; TaMax_C: 125; Cap_Case: 0805; SizeArea_mm2: 2.5; SizeAreaWB_mm2: 6.75; SizeX_mm: 2; SizeY_mm: 1.25; SizeZ_mm: 1.45; AEC Category: Q200
signal-integrity model Cap
simulation model Cap
footprint 0805_HV
footprint 0805_HV1
footprint 0805
footprint 0805M
footprint 0805L
pins: 1, 2

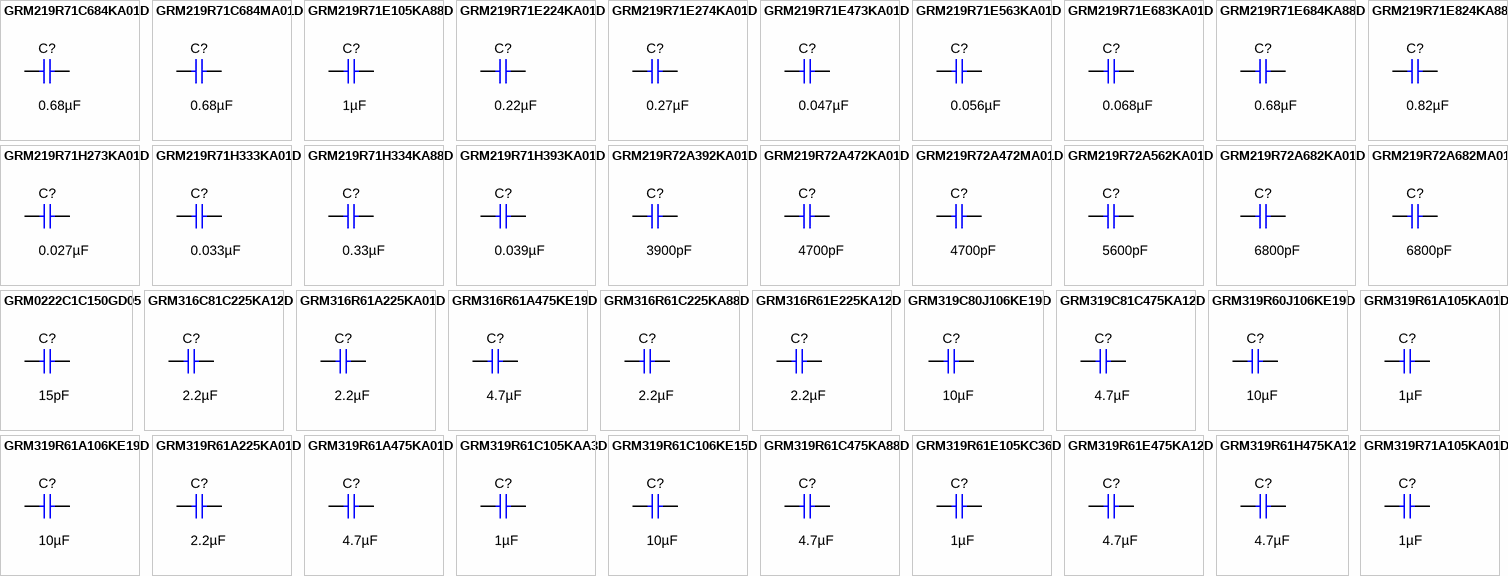
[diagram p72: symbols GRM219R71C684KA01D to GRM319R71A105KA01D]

## GRM219R71C684KA01D
designator C?  ValueDisplayed: 0.68µF  (hidden comment: GRM219R71C684KA01D)
CAP, CERM, 0.68 µF, 16 V,+/- 10%, X7R, 0805; Manufacturer: MuRata; Polarized: N; CompType: Capacitor; Value: 0.68uF; U/M: EA; Cap_F: 0.00000068; Tolerance_%: 10; VDC_V: 16; Value2: 16V; TaMin_C: -55; TaMax_C: 125; Cap_Case: 0805; SizeArea_mm2: 2.5; SizeAreaWB_mm2: 6.75; SizeX_mm: 2; SizeY_mm: 1.25; SizeZ_mm: 1.45; AEC Category: Q200; Green_Lifecycle: Active; Green_REACh: Passed
signal-integrity model Cap
simulation model Cap
footprint 0805_HV
footprint 0805_HV1
footprint 0805
footprint 0805M
footprint 0805L
pins: 1, 2

## GRM219R71C684MA01D
designator C?  ValueDisplayed: 0.68µF  (hidden comment: GRM219R71C684MA01D)
CAP, CERM, 0.68 µF, 16 V,+/- 20%, X7R, 0805; Manufacturer: MuRata; Polarized: N; CompType: Capacitor; Value: 0.68uF; U/M: EA; Cap_F: 0.00000068; Tolerance_%: 20; VDC_V: 16; Value2: 16V; TaMin_C: -55; TaMax_C: 125; Cap_Case: 0805; SizeArea_mm2: 2.5; SizeAreaWB_mm2: 6.75; SizeX_mm: 2; SizeY_mm: 1.25; SizeZ_mm: 1.45; AEC Category: Q200
signal-integrity model Cap
simulation model Cap
footprint 0805_HV
footprint 0805_HV1
footprint 0805
footprint 0805M
footprint 0805L
pins: 1, 2

## GRM219R71E105KA88D
designator C?  ValueDisplayed: 1µF  (hidden comment: GRM219R71E105KA88D)
CAP, CERM, 1 µF, 25 V,+/- 10%, X7R, 0805; Manufacturer: MuRata; Polarized: N; CompType: Capacitor; Value: 1uF; U/M: EA; Cap_F: 0.000001; Tolerance_%: 10; VDC_V: 25; Value2: 25V; TaMin_C: -55; TaMax_C: 125; Cap_Case: 0805; SizeArea_mm2: 2.5; SizeAreaWB_mm2: 6.75; SizeX_mm: 2; SizeY_mm: 1.25; SizeZ_mm: 1.45; AEC Category: Q200; Green_Lifecycle: Active; Green_REACh: Passed
signal-integrity model Cap
simulation model Cap
footprint 0805_HV
footprint 0805_HV1
footprint 0805
footprint 0805M
footprint 0805L
pins: 1, 2

## GRM219R71E224KA01D
designator C?  ValueDisplayed: 0.22µF  (hidden comment: GRM219R71E224KA01D)
CAP, CERM, 0.22 µF, 25 V,+/- 10%, X7R, 0805; Manufacturer: MuRata; Polarized: N; CompType: Capacitor; Value: 0.22uF; U/M: EA; Cap_F: 0.00000022; Tolerance_%: 10; VDC_V: 25; Value2: 25V; TaMin_C: -55; TaMax_C: 125; Cap_Case: 0805; SizeArea_mm2: 2.5; SizeAreaWB_mm2: 6.75; SizeX_mm: 2; SizeY_mm: 1.25; SizeZ_mm: 1.45; AEC Category: Q200
signal-integrity model Cap
simulation model Cap
footprint 0805_HV
footprint 0805_HV1
footprint 0805
footprint 0805M
footprint 0805L
pins: 1, 2

## GRM219R71E274KA01D
designator C?  ValueDisplayed: 0.27µF  (hidden comment: GRM219R71E274KA01D)
CAP, CERM, 0.27 µF, 25 V,+/- 10%, X7R, 0805; Manufacturer: MuRata; Polarized: N; CompType: Capacitor; Value: 0.27uF; U/M: EA; Cap_F: 0.00000027; Tolerance_%: 10; VDC_V: 25; Value2: 25V; TaMin_C: -55; TaMax_C: 125; Cap_Case: 0805; SizeArea_mm2: 2.5; SizeAreaWB_mm2: 6.75; SizeX_mm: 2; SizeY_mm: 1.25; SizeZ_mm: 1.45; AEC Category: Q200
signal-integrity model Cap
simulation model Cap
footprint 0805_HV
footprint 0805_HV1
footprint 0805
footprint 0805M
footprint 0805L
pins: 1, 2

## GRM219R71E473KA01D
designator C?  ValueDisplayed: 0.047µF  (hidden comment: GRM219R71E473KA01D)
CAP, CERM, 0.047 µF, 25 V,+/- 10%, X7R, 0805; Manufacturer: MuRata; Polarized: N; CompType: Capacitor; Value: 0.047uF; U/M: EA; Cap_F: 0.000000047; Tolerance_%: 10; VDC_V: 25; Value2: 25V; TaMin_C: -55; TaMax_C: 125; Cap_Case: 0805; SizeArea_mm2: 2.5; SizeAreaWB_mm2: 6.75; SizeX_mm: 2; SizeY_mm: 1.25; SizeZ_mm: 1.45; AEC Category: Q200
signal-integrity model Cap
simulation model Cap
footprint 0805_HV
footprint 0805_HV1
footprint 0805
footprint 0805M
footprint 0805L
pins: 1, 2

## GRM219R71E563KA01D
designator C?  ValueDisplayed: 0.056µF  (hidden comment: GRM219R71E563KA01D)
CAP, CERM, 0.056 µF, 25 V,+/- 10%, X7R, 0805; Manufacturer: MuRata; Polarized: N; CompType: Capacitor; Value: 0.056uF; U/M: EA; Cap_F: 0.000000056; Tolerance_%: 10; VDC_V: 25; Value2: 25V; TaMin_C: -55; TaMax_C: 125; Cap_Case: 0805; SizeArea_mm2: 2.5; SizeAreaWB_mm2: 6.75; SizeX_mm: 2; SizeY_mm: 1.25; SizeZ_mm: 1.45; AEC Category: Q200
signal-integrity model Cap
simulation model Cap
footprint 0805_HV
footprint 0805_HV1
footprint 0805
footprint 0805M
footprint 0805L
pins: 1, 2

## GRM219R71E683KA01D
designator C?  ValueDisplayed: 0.068µF  (hidden comment: GRM219R71E683KA01D)
CAP, CERM, 0.068 µF, 25 V,+/- 10%, X7R, 0805; Manufacturer: MuRata; Polarized: N; CompType: Capacitor; Value: 0.068uF; U/M: EA; Cap_F: 0.000000068; Tolerance_%: 10; VDC_V: 25; Value2: 25V; TaMin_C: -55; TaMax_C: 125; Cap_Case: 0805; SizeArea_mm2: 2.5; SizeAreaWB_mm2: 6.75; SizeX_mm: 2; SizeY_mm: 1.25; SizeZ_mm: 1.45; AEC Category: Q200; Green_Lifecycle: Active; Green_REACh: Passed
signal-integrity model Cap
simulation model Cap
footprint 0805_HV
footprint 0805_HV1
footprint 0805
footprint 0805M
footprint 0805L
pins: 1, 2

## GRM219R71E684KA88D
designator C?  ValueDisplayed: 0.68µF  (hidden comment: GRM219R71E684KA88D)
CAP, CERM, 0.68 µF, 25 V,+/- 10%, X7R, 0805; Manufacturer: MuRata; Polarized: N; CompType: Capacitor; Value: 0.68uF; U/M: EA; Cap_F: 0.00000068; Tolerance_%: 10; VDC_V: 25; Value2: 25V; TaMin_C: -55; TaMax_C: 125; Cap_Case: 0805; SizeArea_mm2: 2.5; SizeAreaWB_mm2: 6.75; SizeX_mm: 2; SizeY_mm: 1.25; SizeZ_mm: 1.45; AEC Category: Q200
signal-integrity model Cap
simulation model Cap
footprint 0805_HV
footprint 0805_HV1
footprint 0805
footprint 0805M
footprint 0805L
pins: 1, 2

## GRM219R71E824KA88D
designator C?  ValueDisplayed: 0.82µF  (hidden comment: GRM219R71E824KA88D)
CAP, CERM, 0.82 µF, 25 V,+/- 10%, X7R, 0805; Manufacturer: MuRata; Polarized: N; CompType: Capacitor; Value: 0.82uF; U/M: EA; Cap_F: 0.00000082; Tolerance_%: 10; VDC_V: 25; Value2: 25V; TaMin_C: -55; TaMax_C: 125; Cap_Case: 0805; SizeArea_mm2: 2.5; SizeAreaWB_mm2: 6.75; SizeX_mm: 2; SizeY_mm: 1.25; SizeZ_mm: 1.45; AEC Category: Q200
signal-integrity model Cap
simulation model Cap
footprint 0805_HV
footprint 0805_HV1
footprint 0805
footprint 0805M
footprint 0805L
pins: 1, 2

## GRM219R71H273KA01D
designator C?  ValueDisplayed: 0.027µF  (hidden comment: GRM219R71H273KA01D)
CAP, CERM, 0.027 µF, 50 V,+/- 10%, X7R, 0805; Manufacturer: MuRata; Polarized: N; CompType: Capacitor; Value: 0.027uF; U/M: EA; Cap_F: 0.000000027; Tolerance_%: 10; VDC_V: 50; Value2: 50V; TaMin_C: -55; TaMax_C: 125; Cap_Case: 0805; SizeArea_mm2: 2.5; SizeAreaWB_mm2: 6.75; SizeX_mm: 2; SizeY_mm: 1.25; SizeZ_mm: 1.45; AEC Category: Q200
signal-integrity model Cap
simulation model Cap
footprint 0805_HV
footprint 0805_HV1
footprint 0805
footprint 0805M
footprint 0805L
pins: 1, 2

## GRM219R71H333KA01D
designator C?  ValueDisplayed: 0.033µF  (hidden comment: GRM219R71H333KA01D)
CAP, CERM, 0.033 µF, 50 V,+/- 10%, X7R, 0805; Manufacturer: MuRata; Polarized: N; CompType: Capacitor; Value: 0.033uF; U/M: EA; Cap_F: 0.000000033; Tolerance_%: 10; VDC_V: 50; Value2: 50V; TaMin_C: -55; TaMax_C: 125; Cap_Case: 0805; SizeArea_mm2: 2.5; SizeAreaWB_mm2: 6.75; SizeX_mm: 2; SizeY_mm: 1.25; SizeZ_mm: 1.45; AEC Category: Q200
signal-integrity model Cap
simulation model Cap
footprint 0805_HV
footprint 0805_HV1
footprint 0805
footprint 0805M
footprint 0805L
pins: 1, 2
